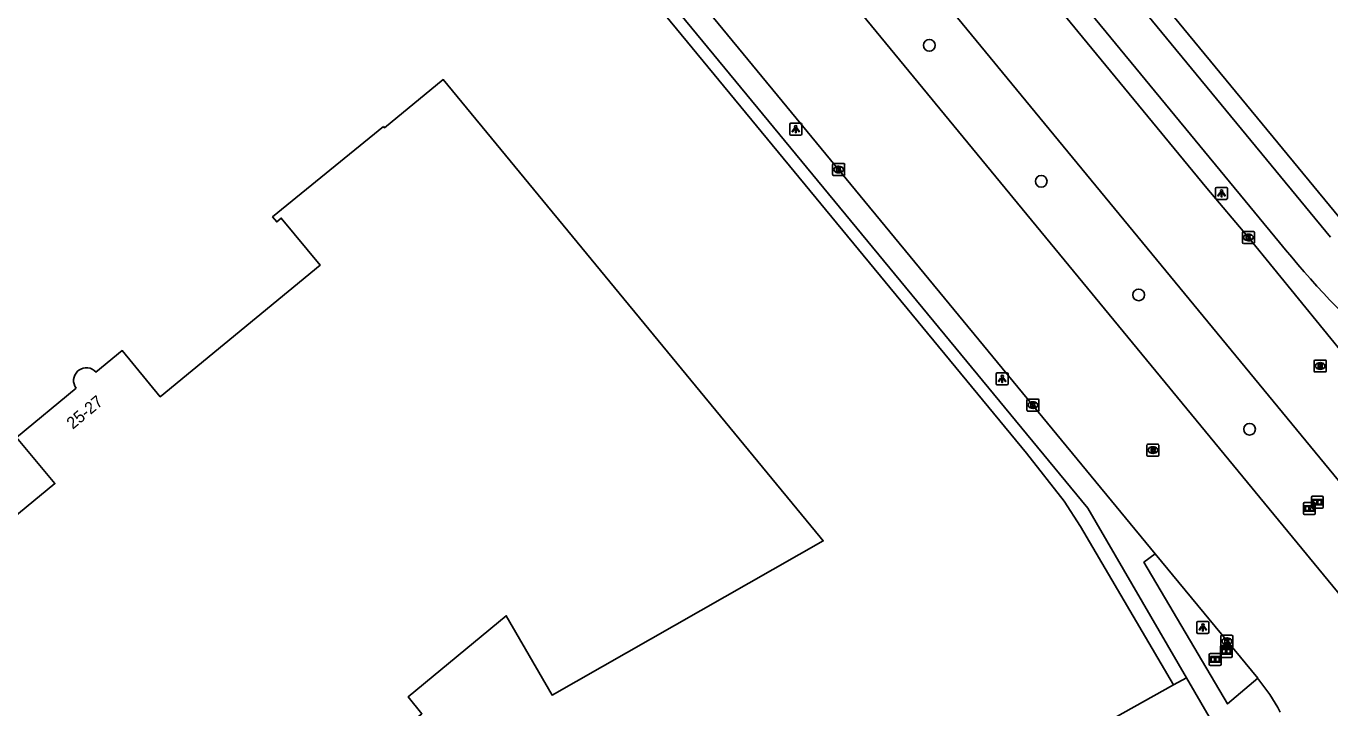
# Model space of a CAD drawing. Extents: x 156141 to 158132, y 385651 to 388399.
# Drawn here: x 157222.2 to 157331.1, y 386235.7 to 386292.7 of the extents above; entities that cross this region are included whole.
import ezdxf

# ---------------------------------------------------------------- set-up
doc = ezdxf.new("R2010")
doc.units = 0
for name, color, linetype in [('IMGEO_Boom', 7, 'Continuous'), ('IMGEO_Fietspad_gesloten', 7, 'Continuous'), ('IMGEO_Groenvoorziening', 7, 'Continuous'), ('IMGEO_Hek', 7, 'Continuous'), ('IMGEO_Informatiebord', 7, 'Continuous'), ('IMGEO_Kolk', 7, 'Continuous'), ('IMGEO_Lichtpunt', 7, 'Continuous'), ('IMGEO_Pand', 7, 'Continuous'), ('IMGEO_Pand_nummerreeks', 7, 'Continuous'), ('IMGEO_Rijbaan_lokaal_gesloten', 7, 'Continuous'), ('IMGEO_Rioolput', 7, 'Continuous'), ('IMGEO_Voetpad_open', 7, 'Continuous')]:
    doc.layers.add(name, color=color, linetype=linetype)

msp = doc.modelspace()

# ---------------------------------------------------------------- linework, layer by layer
at = {"layer": 'IMGEO_Boom'}
for centre in [(157297.61, 386291.1), (157306.96, 386279.74), (157315.1, 386270.25), (157324.36, 386259.03)]:
    msp.add_circle(centre, 0.489, dxfattribs=at)
at = {"layer": 'IMGEO_Fietspad_gesloten'}
for points in [[(157233.28, 386393.84), (157331.13, 386275.06)], [(157230.99, 386391.04), (157326.86, 386274.63)]]:
    msp.add_lwpolyline(points, dxfattribs=at)
msp.add_arc((157386.51, 386322.7), 76.61, 218.8667, 228.4306, dxfattribs=at)
at = {"layer": 'IMGEO_Groenvoorziening'}
for points in [[(157318.01, 386237.67), (157310.24, 386250.89), (157308.88, 386253.01), (157305.74, 386257.03), (157297.07, 386267.54), (157250.02, 386324.6), (157249.12, 386323.86)], [(157319.09, 386238.26), (157318.01, 386237.67)], [(157185.05, 386163.19), (157213.67, 386179.31), (157318.01, 386237.67)]]:
    msp.add_lwpolyline(points, dxfattribs=at)
at = {"layer": 'IMGEO_Hek'}
for points in [[(157297.07, 386267.54), (157250.02, 386324.6), (157233.39, 386310.9)], [(157297.07, 386267.54), (157305.74, 386257.03), (157308.88, 386253.01), (157310.24, 386250.89), (157318.01, 386237.67)], [(157213.67, 386179.31), (157318.01, 386237.67)]]:
    msp.add_lwpolyline(points, dxfattribs=at)
at = {"layer": 'IMGEO_Informatiebord'}
for p, q in [((157329.53, 386252.53), (157329.53, 386253.33)), ((157329.53, 386253.33), (157329.53, 386252.53)), ((157329.63, 386253.43), (157330.42, 386253.43)), ((157330.42, 386253.43), (157329.63, 386253.43)), ((157330.52, 386253.33), (157330.52, 386252.53)), ((157330.52, 386252.53), (157330.52, 386253.33)), ((157328.86, 386252), (157328.86, 386252.8)), ((157328.86, 386252.8), (157328.86, 386252)), ((157328.96, 386252.9), (157329.75, 386252.9)), ((157329.75, 386252.9), (157328.96, 386252.9)), ((157330.42, 386252.43), (157329.63, 386252.43)), ((157329.63, 386252.43), (157330.42, 386252.43)), ((157329.85, 386252.8), (157329.85, 386252)), ((157329.85, 386252), (157329.85, 386252.8)), ((157329.75, 386251.9), (157328.96, 386251.9)), ((157328.96, 386251.9), (157329.75, 386251.9)), ((157320.99, 386239.4), (157320.99, 386240.19)), ((157320.99, 386240.19), (157320.99, 386239.4)), ((157321.09, 386240.29), (157321.88, 386240.29)), ((157321.88, 386240.29), (157321.09, 386240.29)), ((157321.92, 386240.07), (157321.92, 386240.87)), ((157321.92, 386240.87), (157321.92, 386240.07)), ((157321.98, 386240.19), (157321.98, 386239.4)), ((157321.98, 386239.4), (157321.98, 386240.19)), ((157322.02, 386240.97), (157322.81, 386240.97)), ((157322.81, 386240.97), (157322.02, 386240.97)), ((157322.91, 386240.87), (157322.91, 386240.07)), ((157322.91, 386240.07), (157322.91, 386240.87)), ((157321.88, 386239.3), (157321.09, 386239.3)), ((157321.09, 386239.3), (157321.88, 386239.3)), ((157322.81, 386239.97), (157322.02, 386239.97)), ((157322.02, 386239.97), (157322.81, 386239.97))]:
    msp.add_line(p, q, dxfattribs=at)
for points in [[(157329.63, 386253.16), (157330.42, 386253.16), (157330.42, 386252.7), (157329.63, 386252.7), (157329.63, 386253.16)], [(157328.96, 386252.63), (157329.75, 386252.63), (157329.75, 386252.17), (157328.96, 386252.17), (157328.96, 386252.63)], [(157329.03, 386252.57), (157329.03, 386252.23), (157329.3, 386252.23), (157329.3, 386252.44), (157329.41, 386252.44), (157329.41, 386252.23), (157329.69, 386252.23), (157329.69, 386252.57), (157329.41, 386252.57), (157329.41, 386252.48), (157329.3, 386252.48), (157329.31, 386252.57), (157329.03, 386252.57)], [(157329.69, 386253.1), (157329.69, 386252.76), (157329.97, 386252.76), (157329.97, 386252.97), (157330.07, 386252.98), (157330.07, 386252.76), (157330.35, 386252.76), (157330.35, 386253.1), (157330.08, 386253.1), (157330.08, 386253.02), (157329.97, 386253.02), (157329.97, 386253.1), (157329.69, 386253.1)], [(157322.02, 386240.71), (157322.81, 386240.71), (157322.81, 386240.24), (157322.02, 386240.24), (157322.02, 386240.71)], [(157322.08, 386240.64), (157322.08, 386240.31), (157322.36, 386240.31), (157322.36, 386240.52), (157322.46, 386240.52), (157322.47, 386240.31), (157322.74, 386240.31), (157322.74, 386240.64), (157322.47, 386240.64), (157322.47, 386240.56), (157322.36, 386240.56), (157322.36, 386240.64), (157322.08, 386240.64)], [(157321.09, 386240.03), (157321.88, 386240.03), (157321.88, 386239.56), (157321.09, 386239.56), (157321.09, 386240.03)], [(157321.16, 386239.96), (157321.16, 386239.63), (157321.43, 386239.63), (157321.43, 386239.84), (157321.54, 386239.84), (157321.54, 386239.63), (157321.82, 386239.63), (157321.82, 386239.96), (157321.54, 386239.96), (157321.54, 386239.88), (157321.43, 386239.88), (157321.43, 386239.96), (157321.16, 386239.96)]]:
    msp.add_lwpolyline(points, dxfattribs=at)
for centre, start, end in [((157329.63, 386253.33), 90, 180), ((157329.63, 386253.33), 90, 180), ((157330.42, 386253.33), 0, 90), ((157330.42, 386253.33), 360, 90), ((157328.96, 386252.8), 90, 180), ((157328.96, 386252.8), 90, 180), ((157329.63, 386252.53), 180, 270), ((157329.63, 386252.53), 180, 270), ((157329.75, 386252.8), 0, 90), ((157329.75, 386252.8), 360, 90), ((157330.42, 386252.53), 270, 0), ((157330.42, 386252.53), 270, 0), ((157328.96, 386252), 180, 270), ((157328.96, 386252), 180, 270), ((157329.75, 386252), 270, 0), ((157329.75, 386252), 270, 0), ((157321.09, 386240.19), 90, 180), ((157321.09, 386240.19), 90, 180), ((157321.88, 386240.19), 0, 90), ((157321.88, 386240.19), 360, 90), ((157322.02, 386240.87), 90, 180), ((157322.02, 386240.87), 90, 180), ((157322.02, 386240.07), 180, 270), ((157322.02, 386240.07), 180, 270), ((157322.81, 386240.87), 0, 90), ((157322.81, 386240.87), 360, 90), ((157322.81, 386240.07), 270, 0), ((157322.81, 386240.07), 270, 0), ((157321.09, 386239.4), 180, 270), ((157321.09, 386239.4), 180, 270), ((157321.88, 386239.4), 270, 0), ((157321.88, 386239.4), 270, 0)]:
    msp.add_arc(centre, 0.1, start, end, dxfattribs=at)
at = {"layer": 'IMGEO_Kolk'}
for p, q in [((157289.54, 386280.3), (157289.54, 386281.15)), ((157289.62, 386281.22), (157290.47, 386281.22)), ((157290.03, 386281), (157290.05, 386281)), ((157290.05, 386280.44), (157290.03, 386280.44)), ((157290.54, 386281.15), (157290.54, 386280.3)), ((157290.47, 386280.22), (157289.62, 386280.22)), ((157323.76, 386274.62), (157323.76, 386275.47)), ((157323.84, 386275.55), (157324.69, 386275.55)), ((157324.25, 386275.33), (157324.27, 386275.33)), ((157324.76, 386275.47), (157324.76, 386274.62)), ((157324.69, 386274.55), (157323.84, 386274.55)), ((157324.27, 386274.77), (157324.25, 386274.77)), ((157305.77, 386260.62), (157305.77, 386261.47)), ((157305.85, 386261.55), (157306.7, 386261.55)), ((157306.26, 386261.33), (157306.29, 386261.33)), ((157306.28, 386260.77), (157306.26, 386260.77)), ((157306.77, 386261.47), (157306.77, 386260.62)), ((157306.7, 386260.55), (157305.85, 386260.55)), ((157321.97, 386240.88), (157321.97, 386241.73)), ((157322.04, 386241.81), (157322.89, 386241.81)), ((157322.45, 386241.59), (157322.48, 386241.59)), ((157322.97, 386241.73), (157322.97, 386240.88)), ((157322.89, 386240.81), (157322.04, 386240.81)), ((157322.48, 386241.03), (157322.45, 386241.03))]:
    msp.add_line(p, q, dxfattribs=at)
for points in [[(157289.54, 386280.3), (157289.54, 386281.15)], [(157289.62, 386281.22), (157290.47, 386281.22)], [(157289.86, 386280.92), (157289.99, 386280.92), (157289.99, 386280.77), (157290.11, 386280.92), (157290.28, 386280.92), (157290.13, 386280.77), (157290.29, 386280.52), (157290.13, 386280.52), (157290.05, 386280.69), (157289.99, 386280.62), (157289.99, 386280.52), (157289.86, 386280.52), (157289.86, 386280.92)], [(157290.54, 386281.15), (157290.54, 386280.3)], [(157290.47, 386280.22), (157289.62, 386280.22)], [(157323.76, 386274.62), (157323.76, 386275.47)], [(157323.84, 386275.55), (157324.69, 386275.55)], [(157324.08, 386275.25), (157324.21, 386275.25), (157324.21, 386275.1), (157324.33, 386275.25), (157324.5, 386275.25), (157324.35, 386275.1), (157324.51, 386274.85), (157324.35, 386274.85), (157324.27, 386275.01), (157324.21, 386274.94), (157324.21, 386274.85), (157324.08, 386274.85), (157324.08, 386275.25)], [(157324.76, 386275.47), (157324.76, 386274.62)], [(157324.69, 386274.55), (157323.84, 386274.55)], [(157305.77, 386260.62), (157305.77, 386261.47)], [(157305.85, 386261.55), (157306.7, 386261.55)], [(157306.09, 386261.25), (157306.22, 386261.25), (157306.22, 386261.09), (157306.35, 386261.25), (157306.51, 386261.25), (157306.36, 386261.1), (157306.52, 386260.85), (157306.36, 386260.85), (157306.28, 386261.01), (157306.22, 386260.94), (157306.22, 386260.85), (157306.09, 386260.85), (157306.09, 386261.25)], [(157306.77, 386261.47), (157306.77, 386260.62)], [(157306.7, 386260.55), (157305.85, 386260.55)], [(157321.97, 386240.88), (157321.97, 386241.73)], [(157322.04, 386241.81), (157322.89, 386241.81)], [(157322.29, 386241.51), (157322.41, 386241.51), (157322.41, 386241.36), (157322.54, 386241.51), (157322.7, 386241.51), (157322.56, 386241.36), (157322.71, 386241.11), (157322.56, 386241.11), (157322.47, 386241.27), (157322.41, 386241.21), (157322.41, 386241.11), (157322.29, 386241.11), (157322.29, 386241.51)], [(157322.97, 386241.73), (157322.97, 386240.88)], [(157322.89, 386240.81), (157322.04, 386240.81)]]:
    msp.add_lwpolyline(points, dxfattribs=at)
for centre, start, end in [((157289.62, 386281.15), 91.552, 178.448), ((157289.62, 386281.15), 91.552, 178.448), ((157290.47, 386281.15), 1.552, 88.448), ((157290.47, 386281.15), 1.552, 88.448), ((157289.62, 386280.3), 181.552, 268.448), ((157289.62, 386280.3), 181.552, 268.448), ((157290.47, 386280.3), 271.552, 358.448), ((157290.47, 386280.3), 271.552, 358.448), ((157323.84, 386275.47), 91.552, 178.448), ((157323.84, 386275.47), 91.552, 178.448), ((157324.69, 386275.47), 1.552, 88.448), ((157324.69, 386275.47), 1.552, 88.448), ((157323.84, 386274.62), 181.552, 268.448), ((157323.84, 386274.62), 181.552, 268.448), ((157324.69, 386274.62), 271.552, 358.448), ((157324.69, 386274.62), 271.552, 358.448), ((157305.85, 386261.47), 91.552, 178.448), ((157305.85, 386261.47), 91.552, 178.448), ((157306.7, 386261.47), 1.552, 88.448), ((157306.7, 386261.47), 1.552, 88.448), ((157305.85, 386260.62), 181.552, 268.448), ((157305.85, 386260.62), 181.552, 268.448), ((157306.7, 386260.62), 271.552, 358.448), ((157306.7, 386260.62), 271.552, 358.448), ((157322.04, 386241.73), 91.552, 178.448), ((157322.04, 386241.73), 91.552, 178.448), ((157322.89, 386241.73), 1.552, 88.448), ((157322.89, 386241.73), 1.552, 88.448), ((157322.04, 386240.88), 181.552, 268.448), ((157322.04, 386240.88), 181.552, 268.448), ((157322.89, 386240.88), 271.552, 358.448), ((157322.89, 386240.88), 271.552, 358.448)]:
    msp.add_arc(centre, 0.0765, start, end, dxfattribs=at)
for centre, major_axis, ratio, start_param, end_param in [((157290.03, 386280.72), (-0.387, 0.002), 0.722429, 4.712389, 7.853982), ((157290.05, 386280.72), (-0.39, 0.002), 0.717154, 1.570796, 4.712389), ((157324.25, 386275.05), (-0.387, 0.002), 0.722429, 4.712389, 7.853982), ((157324.27, 386275.05), (-0.39, 0.002), 0.717154, 1.570796, 4.712389), ((157306.26, 386261.05), (-0.387, 0.002), 0.722429, 4.712389, 7.853982), ((157306.28, 386261.05), (-0.39, 0.002), 0.717154, 1.570796, 4.712389), ((157322.45, 386241.31), (-0.387, 0.002), 0.722429, 4.712389, 7.853982), ((157322.48, 386241.31), (-0.39, 0.002), 0.717154, 1.570796, 4.712389)]:
    msp.add_ellipse(centre, major_axis=major_axis, ratio=ratio, start_param=start_param, end_param=end_param, dxfattribs=at)
at = {"layer": 'IMGEO_Lichtpunt'}
for p, q in [((157285.96, 386284.49), (157285.96, 386283.69)), ((157285.96, 386284.49), (157285.96, 386283.69)), ((157286.86, 386284.59), (157286.05, 386284.59)), ((157286.86, 386284.59), (157286.05, 386284.59)), ((157286.96, 386283.69), (157286.96, 386284.49)), ((157286.96, 386283.69), (157286.96, 386284.49)), ((157286.05, 386283.59), (157286.86, 386283.59)), ((157286.05, 386283.59), (157286.86, 386283.59)), ((157321.52, 386279.14), (157321.52, 386278.33)), ((157321.52, 386279.14), (157321.52, 386278.33)), ((157322.42, 386279.23), (157321.62, 386279.23)), ((157322.42, 386279.23), (157321.62, 386279.23)), ((157321.62, 386278.23), (157322.42, 386278.23)), ((157321.62, 386278.23), (157322.42, 386278.23)), ((157322.52, 386278.33), (157322.52, 386279.14)), ((157322.52, 386278.33), (157322.52, 386279.14)), ((157303.2, 386263.64), (157303.2, 386262.83)), ((157303.2, 386263.64), (157303.2, 386262.83)), ((157304.1, 386263.73), (157303.29, 386263.73)), ((157304.1, 386263.73), (157303.29, 386263.73)), ((157304.2, 386262.83), (157304.2, 386263.64)), ((157304.2, 386262.83), (157304.2, 386263.64)), ((157303.29, 386262.74), (157304.1, 386262.74)), ((157303.29, 386262.74), (157304.1, 386262.74)), ((157319.96, 386242.87), (157319.96, 386242.07)), ((157319.96, 386242.87), (157319.96, 386242.07)), ((157320.86, 386242.97), (157320.05, 386242.97)), ((157320.86, 386242.97), (157320.05, 386242.97)), ((157320.95, 386242.07), (157320.95, 386242.87)), ((157320.95, 386242.07), (157320.95, 386242.87)), ((157320.05, 386241.97), (157320.86, 386241.97)), ((157320.05, 386241.97), (157320.86, 386241.97))]:
    msp.add_line(p, q, dxfattribs=at)
for points in [[(157286.33, 386284.16), (157286.37, 386284.13), (157286.19, 386283.87), (157286.15, 386283.9), (157286.33, 386284.16)], [(157286.44, 386284.11), (157286.48, 386284.11), (157286.48, 386283.79), (157286.44, 386283.79), (157286.44, 386284.11)], [(157286.55, 386284.13), (157286.58, 386284.16), (157286.77, 386283.89), (157286.73, 386283.87), (157286.55, 386284.13)], [(157321.9, 386278.8), (157321.93, 386278.77), (157321.75, 386278.51), (157321.71, 386278.54), (157321.9, 386278.8)], [(157322, 386278.75), (157322.05, 386278.75), (157322.05, 386278.43), (157322, 386278.43), (157322, 386278.75)], [(157322.11, 386278.77), (157322.15, 386278.8), (157322.33, 386278.54), (157322.29, 386278.51), (157322.11, 386278.77)], [(157303.57, 386263.3), (157303.61, 386263.27), (157303.42, 386263.01), (157303.39, 386263.04), (157303.57, 386263.3)], [(157303.67, 386263.25), (157303.72, 386263.25), (157303.72, 386262.93), (157303.67, 386262.93), (157303.67, 386263.25)], [(157303.78, 386263.27), (157303.82, 386263.3), (157304.01, 386263.04), (157303.97, 386263.01), (157303.78, 386263.27)], [(157320.33, 386242.54), (157320.37, 386242.51), (157320.18, 386242.25), (157320.14, 386242.27), (157320.33, 386242.54)], [(157320.43, 386242.49), (157320.48, 386242.49), (157320.48, 386242.17), (157320.43, 386242.17), (157320.43, 386242.49)], [(157320.54, 386242.51), (157320.58, 386242.54), (157320.77, 386242.27), (157320.73, 386242.25), (157320.54, 386242.51)]]:
    msp.add_lwpolyline(points, dxfattribs=at)
for centre in [(157286.46, 386284.29), (157322.02, 386278.93), (157303.7, 386263.44), (157320.46, 386242.67)]:
    msp.add_circle(centre, 0.0994, dxfattribs=at)
for centre, start, end in [((157286.05, 386284.49), 90, 180), ((157286.05, 386284.49), 90, 180), ((157286.05, 386283.69), 180, 270), ((157286.05, 386283.69), 180, 270), ((157286.86, 386284.49), 0, 90), ((157286.86, 386284.49), 0, 90), ((157286.86, 386283.69), 270, 0), ((157286.86, 386283.69), 270, 360), ((157321.62, 386279.14), 90, 180), ((157321.62, 386279.14), 90, 180), ((157321.62, 386278.33), 180, 270), ((157321.62, 386278.33), 180, 270), ((157322.42, 386279.14), 0, 90), ((157322.42, 386279.14), 0, 90), ((157322.42, 386278.33), 270, 0), ((157322.42, 386278.33), 270, 360), ((157303.29, 386263.64), 90, 180), ((157303.29, 386263.64), 90, 180), ((157304.1, 386263.64), 0, 90), ((157304.1, 386263.64), 0, 90), ((157303.29, 386262.83), 180, 270), ((157303.29, 386262.83), 180, 270), ((157304.1, 386262.83), 270, 0), ((157304.1, 386262.83), 270, 360), ((157320.05, 386242.87), 90, 180), ((157320.05, 386242.87), 90, 180), ((157320.86, 386242.87), 0, 90), ((157320.86, 386242.87), 0, 90), ((157320.05, 386242.07), 180, 270), ((157320.05, 386242.07), 180, 270), ((157320.86, 386242.07), 270, 0), ((157320.86, 386242.07), 270, 360)]:
    msp.add_arc(centre, 0.0946, start, end, dxfattribs=at)
at = {"layer": 'IMGEO_Pand'}
for points in [[(157252.02, 386284.32), (157252.12, 386284.2), (157257.02, 386288.24), (157288.5, 386250), (157288.75, 386249.7), (157266.1, 386236.82), (157262.28, 386243.44), (157254.08, 386236.66), (157255.23, 386235.26), (157246.3, 386227.92), (157245.15, 386229.36), (157210.23, 386200.57), (157189.57, 386225.68), (157219.12, 386250), (157224.58, 386254.49), (157221.38, 386258.33), (157226.35, 386262.46)], [(157228.01, 386263.8), (157230.21, 386265.6), (157233.38, 386261.74), (157246.73, 386272.73), (157243.49, 386276.67), (157243.11, 386276.35), (157242.76, 386276.77), (157252.02, 386284.32)], [(157226.48, 386263.87), (157226.57, 386263.95)]]:
    msp.add_lwpolyline(points, dxfattribs=at)
for start, end in [(41.3876, 126.3167), (133.1187, 216.1193)]:
    msp.add_arc((157227.21, 386263.09), 1.07, start, end, dxfattribs=at)
at = {"layer": 'IMGEO_Rijbaan_lokaal_gesloten'}
for points in [[(157349.18, 386247.25), (157332.61, 386264.8), (157324.26, 386275.05), (157320.8, 386279.16), (157212.17, 386411.12), (157210.79, 386412.79), (157209.6, 386414.65)], [(157203.78, 386410.2), (157205.76, 386407.83), (157335.68, 386250), (157341.4, 386242.71), (157342.29, 386241.55)], [(157337.29, 386238.67), (157336.11, 386240.1), (157327.94, 386250), (157201.15, 386404.03), (157199.19, 386406.39)], [(157265.45, 386312.07), (157270.55, 386304.5), (157271.76, 386302.91), (157316.48, 386248.62)], [(157316.48, 386248.62), (157325.05, 386238.22)]]:
    msp.add_lwpolyline(points, dxfattribs=at)
msp.add_arc((157311.33, 386227.05), 17.68, 28.1947, 39.1572, dxfattribs=at)
at = {"layer": 'IMGEO_Rioolput'}
for p, q in [((157329.76, 386263.88), (157329.76, 386264.73)), ((157329.84, 386264.81), (157330.69, 386264.81)), ((157330.25, 386264.59), (157330.27, 386264.59)), ((157330.27, 386264.03), (157330.25, 386264.03)), ((157330.76, 386264.73), (157330.76, 386263.88)), ((157330.69, 386263.81), (157329.84, 386263.81)), ((157315.79, 386256.86), (157315.79, 386257.71)), ((157315.86, 386257.79), (157316.72, 386257.79)), ((157316.28, 386257.57), (157316.3, 386257.57)), ((157316.79, 386257.71), (157316.79, 386256.86)), ((157316.72, 386256.79), (157315.86, 386256.79)), ((157316.3, 386257.01), (157316.27, 386257.01))]:
    msp.add_line(p, q, dxfattribs=at)
for points in [[(157329.76, 386263.88), (157329.76, 386264.73)], [(157329.84, 386264.81), (157330.69, 386264.81)], [(157330.35, 386264.51), (157330.1, 386264.51), (157330.1, 386264.11)], [(157330.1, 386264.11), (157330.22, 386264.11), (157330.22, 386264.27), (157330.23, 386264.27)], [(157330.28, 386264.43), (157330.22, 386264.43), (157330.22, 386264.35)], [(157330.22, 386264.35), (157330.27, 386264.35)], [(157330.28, 386264.24), (157330.35, 386264.11), (157330.49, 386264.11), (157330.43, 386264.23)], [(157330.76, 386264.73), (157330.76, 386263.88)], [(157330.69, 386263.81), (157329.84, 386263.81)], [(157315.79, 386256.86), (157315.79, 386257.71)], [(157315.86, 386257.79), (157316.72, 386257.79)], [(157316.38, 386257.48), (157316.13, 386257.49), (157316.13, 386257.09)], [(157316.79, 386257.71), (157316.79, 386256.86)], [(157316.72, 386256.79), (157315.86, 386256.79)], [(157316.13, 386257.09), (157316.25, 386257.09), (157316.25, 386257.25), (157316.26, 386257.25)], [(157316.3, 386257.41), (157316.25, 386257.41), (157316.25, 386257.32)], [(157316.25, 386257.32), (157316.3, 386257.32)], [(157316.31, 386257.22), (157316.38, 386257.09), (157316.52, 386257.09), (157316.45, 386257.21)]]:
    msp.add_lwpolyline(points, dxfattribs=at)
for centre, radius, start, end in [((157329.84, 386264.73), 0.0765, 91.552, 178.448), ((157329.84, 386264.73), 0.0765, 91.552, 178.448), ((157330.23, 386264.22), 0.0533, 26.0293, 88.6989), ((157330.26, 386264.54), 0.19, 274.7715, 282.9687), ((157330.28, 386264.33), 0.0964, 77.0061, 93.1865), ((157330.3, 386264.39), 0.0378, 276.6634, 79.6772), ((157330.35, 386264.4), 0.109, 350.3612, 89.416), ((157330.35, 386264.4), 0.112, 277.5842, 350.9817), ((157330.33, 386264.18), 0.108, 29.5134, 73.7905), ((157330.69, 386264.73), 0.0765, 1.552, 88.448), ((157330.69, 386264.73), 0.0765, 1.552, 88.448), ((157329.84, 386263.88), 0.0765, 181.552, 268.448), ((157329.84, 386263.88), 0.0765, 181.552, 268.448), ((157330.69, 386263.88), 0.0765, 271.552, 358.448), ((157330.69, 386263.88), 0.0765, 271.552, 358.448), ((157315.87, 386257.71), 0.0765, 91.552, 178.448), ((157315.87, 386257.71), 0.0765, 91.552, 178.448), ((157316.38, 386257.37), 0.109, 350.3612, 89.416), ((157316.71, 386257.71), 0.0765, 1.552, 88.448), ((157316.71, 386257.71), 0.0765, 1.552, 88.448), ((157315.87, 386256.86), 0.0765, 181.552, 268.448), ((157315.87, 386256.86), 0.0765, 181.552, 268.448), ((157316.26, 386257.2), 0.0533, 26.0293, 88.6989), ((157316.31, 386257.31), 0.0964, 77.0061, 93.1865), ((157316.29, 386257.51), 0.19, 274.7715, 282.9687), ((157316.32, 386257.37), 0.0378, 276.6634, 79.6772), ((157316.38, 386257.37), 0.112, 277.5842, 350.9817), ((157316.36, 386257.16), 0.108, 29.5134, 73.7905), ((157316.71, 386256.86), 0.0765, 271.552, 358.448), ((157316.71, 386256.86), 0.0765, 271.552, 358.448)]:
    msp.add_arc(centre, radius, start, end, dxfattribs=at)
for centre, major_axis, ratio, start_param, end_param in [((157330.25, 386264.31), (-0.387, 0.002), 0.722429, 4.712389, 7.853982), ((157330.27, 386264.31), (-0.39, 0.002), 0.717154, 1.570796, 4.712389), ((157316.28, 386257.29), (-0.387, 0.002), 0.722429, 4.712389, 7.853982), ((157316.3, 386257.29), (-0.39, 0.002), 0.717154, 1.570796, 4.712389)]:
    msp.add_ellipse(centre, major_axis=major_axis, ratio=ratio, start_param=start_param, end_param=end_param, dxfattribs=at)
at = {"layer": 'IMGEO_Voetpad_open'}
for points in [[(157332.34, 386276.12), (157234.23, 386395.17)], [(157250.61, 386325.49), (157310.85, 386252.42), (157319.09, 386238.26)], [(157325.05, 386238.22), (157322.52, 386236.08), (157315.54, 386247.91), (157316.48, 386248.62)], [(157319.09, 386238.26), (157322.19, 386232.95)]]:
    msp.add_lwpolyline(points, dxfattribs=at)

# ---------------------------------------------------------------- texts
at = {"layer": 'IMGEO_Pand_nummerreeks'}
msp.add_text('25-27', height=1, rotation=39.7575, dxfattribs=at).set_placement((157226.07, 386258.98))

doc.saveas('drawing.dxf')
